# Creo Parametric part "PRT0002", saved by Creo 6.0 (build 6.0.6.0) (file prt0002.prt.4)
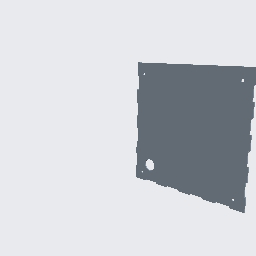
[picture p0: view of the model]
Units: Inch lbm Second (Pro/E Default); INCH, POUND, SECS

Created from: INLBS_PART_SOLID.PRT

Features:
  1. datum plane "RIGHT"
  2. datum plane "TOP"
  3. datum plane "FRONT"
  4. coordinate system
  5. sketch "Sketch 1"
  6. extrusion "Extrude 1"
  7. sketch "Sketch 2"
  8. extruded cut "Extrude 2"
  9. sketch "Sketch 3"
  10. extruded cut "Extrude 3"

Surfaces: 54 plane, 5 cylinder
